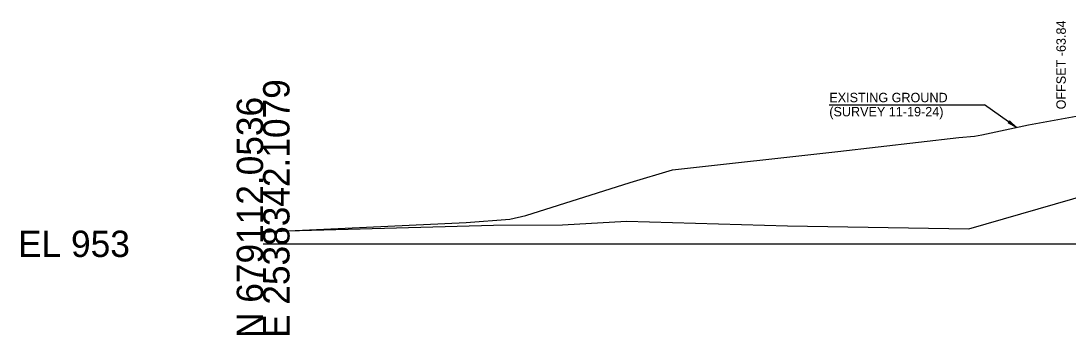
# Model space of a CAD drawing. Extents: x -26 to 1603, y -30 to 14537.
# Drawn here: x -25.7 to 85.4, y 2990.3 to 3023.7 of the extents above; entities that cross this region are included whole.
import ezdxf

# ---------------------------------------------------------------- set-up
doc = ezdxf.new("R2010")
doc.units = 0
for name, color, linetype in [('DESIGN - SHEET - Light Grid', 7, 'Continuous'), ('DESIGN - TYPICAL - Slope Tie Text', 7, 'Continuous'), ('SURVEY - GROUND - Top of Ground', 7, 'Continuous')]:
    doc.layers.add(name, color=color, linetype=linetype)

msp = doc.modelspace()

# ---------------------------------------------------------------- linework, layer by layer
at = {"layer": 'DESIGN - SHEET - Light Grid'}
msp.add_line((0, 3000), (150, 3000), dxfattribs=at)
at = {"layer": 'SURVEY - GROUND - Top of Ground'}
for p in [(60.07, 3014.75), (79.92, 3012.36)]:
    msp.add_line(p, (76.55, 3014.75), dxfattribs=at)
for points in [[(0, 3001.3), (24.44, 3001.97), (31.75, 3002.01), (38.56, 3002.42), (55.63, 3001.91), (74.86, 3001.61), (91.41, 3006.36), (113.43, 3010.39), (121.54, 3014.45), (128.66, 3014.62), (142.41, 3015.26), (150, 3015.51), (165.55, 3016), (189.78, 3017.18), (206.28, 3017.32), (238.97, 3017.63), (251.02, 3017.71), (286.47, 3017.12), (298.09, 3016.89), (300, 3016.85)], [(0, 3001.25), (2.66, 3001.37), (21.56, 3002.26), (26.19, 3002.63), (27.89, 3003.02), (38.93, 3006.52), (43.42, 3007.85), (60.98, 3009.8), (73.83, 3011.29), (75.48, 3011.43), (76.26, 3011.56), (81.21, 3012.64), (86.65, 3013.62)], [(79.92, 3012.36), (79.03, 3012.84), (79.21, 3012.87), (79.18, 3013.05), (79.92, 3012.36)]]:
    msp.add_lwpolyline(points, dxfattribs=at)
msp.add_lwpolyline([(79.92, 3012.36), (79.03, 3012.84), (79.21, 3012.87), (79.18, 3013.05)], close=True, dxfattribs=at)

# ---------------------------------------------------------------- texts
at = {"layer": 'DESIGN - SHEET - Light Grid'}
for s, p in [('E 2538342.1079', (2.8, 2990)), ('N 679112.0536', (0, 2990))]:
    msp.add_text(s, height=2.8, rotation=90, dxfattribs=at).set_placement(p)
msp.add_text('EL 953', height=2.8, dxfattribs=at).set_placement((-26, 2998.6))
at = {"layer": 'DESIGN - TYPICAL - Slope Tie Text'}
msp.add_text('OFFSET -63.84', height=1, rotation=90, dxfattribs=at).set_placement((85.16, 3014.28))
at = {"layer": 'SURVEY - GROUND - Top of Ground'}
for s, p in [('EXISTING GROUND', (60.07, 3015.04)), ('(SURVEY 11-19-24)', (60.07, 3013.54))]:
    msp.add_text(s, height=1, dxfattribs=at).set_placement(p)

doc.saveas('drawing.dxf')
